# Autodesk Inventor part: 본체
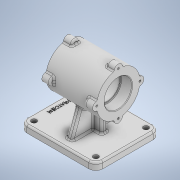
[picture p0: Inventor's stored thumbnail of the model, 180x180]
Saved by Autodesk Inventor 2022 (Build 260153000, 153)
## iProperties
Created: 2023-05
Part Number: 본체
Material: 일반
Document SubType Name: Modeling
Designer: Admin
Density: 1 g/cm^3
Appearance: 기본값
Author: Admin
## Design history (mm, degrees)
sketch "스케치1"
  geometry: L1 (0, -7.4)-(0, 44.4) reference; L2 (-60.9, 0)-(60.9, 0) reference; L3 (-43.5, 0)-(43.5, 0); L4 (43.5, 0)-(43.5, 37); L5 (43.5, 37)-(-43.5, 37); L6 (-43.5, 37)-(-43.5, 0); 2 further points
  constraints: 8 end point, 2 parallel, 1 horizontal, 1 perpendicular, 1 point on line, 1 other
  dimensions: "d4" = 87 distance between parallel lines of L4 L6; "d5" = 74 diameter of L5 L2
revolve "회전1" sketch "스케치1" stored, may be unused: angle "d6" = 90 deg
sketch "스케치2"
  geometry: L1 (-43.5, -37)-(-43.5, 37) reference; L2 (-43.5, 0)-(-24.5, 0); L3 (-24.5, 0)-(-24.5, 23.5); L4 (-24.5, 23.5)-(-43.5, 23.5); L5 (-43.5, 23.5)-(-43.5, 0); L6 (-24.5, 0)-(24.5, 0); L7 (24.5, 0)-(24.5, 21); L8 (24.5, 21)-(-24.5, 21); L9 (-24.5, 21)-(-24.5, 0); L10 (43.5, -37)-(43.5, 37) reference; L11 (24.5, 0)-(43.5, 0); L12 (43.5, 0)-(43.5, 23.5); L13 (43.5, 23.5)-(24.5, 23.5); L14 (24.5, 23.5)-(24.5, 0); L15 (-60.9, 0)-(60.9, 0) reference; 3 further points
  constraints: 24 end point, 6 parallel, 3 horizontal, 3 perpendicular, 2 point on line, 1 midpoint
  dimensions: "d7" = 47 diameter of L4 L15; "d8" = 42 diameter of L8 L15; "d9" = 19 distance between parallel lines of L5 L3; "d10" = 19 distance between parallel lines of L10 L7
revolve "회전2" sketch "스케치2" stored, may be unused: angle "d11" = 90 deg
node "작업 평면1"
sketch "스케치3"
  geometry: L1 (70, -55)-(-60, -55); L2 (-60, -55)-(-60, 55); L3 (-60, 55)-(70, 55); L4 (70, 55)-(70, -55); L5 (89.368, 0)-(-92.632, 0) reference; L6 (0, -67.146)-(0, 86.854) reference; 1 further point
  constraints: 8 end point, 2 parallel, 1 horizontal, 1 perpendicular, 1 other
  dimensions: "d14" = 110 distance between parallel lines of L3 L1; "d58" = 130 distance between parallel lines of L2 L4; "d59" = 70 distance between parallel lines of L6 L4
extrude "돌출1" join sketch "스케치3" distance "d15" = 12; taper "d16" = 0 deg
sketch "스케치4"
  geometry: L1 (-20, 5)-(20, 5); L2 (20, 5)-(20, -5); L3 (20, -5)-(-20, -5); L4 (-20, -5)-(-20, 5); L5 (-96, 0)-(86, 0) reference; L6 (0, 77)-(0, -77) reference; 1 further point
  constraints: 8 end point, 2 parallel, 1 horizontal, 1 perpendicular, 2 other
  dimensions: "d17" = 10 distance between parallel lines of L3 L1; "d18" = 40 distance between parallel lines of L2 L4
extrude "돌출2" join sketch "스케치4" stored distance "d19" = 12; taper "d20" = 0 deg
sketch "스케치5"
  geometry: L1 (0, -105.8)-(0, 60.8) reference; C1 r 7 at (0, 37); 2 further points
  constraints: 1 centre point, 1 point on line, 1 vertical alignment, 1 other
  dimensions: "d21" = 14 diameter of C1
extrude "돌출3" join sketch "스케치5" distance "d22" = 14; taper "d23" = 0 deg
sketch "스케치7"
  geometry: A1 r 7 centre (0, 0) between (6.969, -0.662) and (-6.969, -0.662) reference; A2 r 7 centre (37, -37) between (36.338, -43.969) and (36.338, -30.031) reference; A3 r 7 centre (0, -74) between (-6.969, -73.338) and (6.969, -73.338) reference; A4 r 7 centre (-37, -37) between (-36.338, -30.031) and (-36.338, -43.969) reference; 5 further points
  constraints: 4 coincident
hole "구멍1" sketch "스케치7" at (0, 0), (37, -37), (0, -74), (-37, -37) diameter "d27" = 3.242; stored, may be unused: countersink angle "d31" = 90 deg, drill point angle "d33" = 118 deg; dims "d28" = 8, "d29" = 4, "d30" = 2, "d32" = 10
sketch "스케치8"
  geometry: C1 r 1.621 at (74, 0) reference; C2 r 1.621 at (37, -37) reference; C3 r 1.621 at (0, 0) reference; A1 r 7 centre (37, 37) between (43.969, 36.338) and (30.031, 36.338) reference; A2 r 7 centre (0, 0) between (0.662, 6.969) and (0.662, -6.969) reference; A3 r 7 centre (37, -37) between (30.031, -36.338) and (43.969, -36.338) reference; A4 r 7 centre (74, 0) between (73.338, -6.969) and (73.338, 6.969) reference; 5 further points
  constraints: 4 coincident
hole "구멍2" sketch "스케치8" at (37, 37), (74, 0), (37, -37), (0, 0) diameter "d34" = 3.242; stored, may be unused: countersink angle "d38" = 90 deg, drill point angle "d40" = 118 deg; dims "d35" = 8, "d36" = 4, "d37" = 2, "d39" = 10
sketch "스케치9"
  geometry: L1 (-70, -55)-(-70, 55) reference; L2 (-70, 41)-(-26.964, 25.336); L3 (-82, 55)-(-70, 55) reference; A1 r 37 centre (0, 0) between (-6.969, 36.338) and (-36.338, 6.969) reference; 1 further point
  constraints: 2 end point, 1 point on circle, 1 point on line
  dimensions: "d41" = 110 deg angle of L1 L2; "d42" = 14 distance from line of L2.start L3
feature "리브1" sketch "스케치9" dims "d43" = 1, "d44" = 10, "d45" = 0, "d46" = 0, "d47" = 1, "d48" = 1
fillet "모깎기1" dims "d49" = 12
sketch "스케치10"
  geometry: A1 r 12 centre (-58, 43) between (-58, 55) and (-70, 43) reference; A2 r 12 centre (-58, -43) between (-70, -43) and (-58, -55) reference; A3 r 12 centre (48, 43) between (60, 43) and (48, 55) reference; A4 r 12 centre (48, -43) between (48, -55) and (60, -43) reference; 5 further points
  constraints: 4 coincident
hole "구멍3" sketch "스케치10" at (-58, 43), (48, 43), (48, -43), (-58, -43) diameter "d50" = 9; stored, may be unused: countersink angle "d54" = 90 deg, drill point angle "d56" = 0 deg; dims "d51" = 8, "d52" = 4, "d53" = 2, "d55" = 10
sketch "스케치11"
  geometry: L1 (0, 77)-(0, -77) reference; L2 (-96, 0)-(86, 0) reference; 2 further points
  constraints: 1 other
  dimensions: "d57" = 58 distance from line of L1 point (-58, 1.636)
feature "엠보싱1" dims "d4" = 87, "d5" = 74, "d7" = 47, "d8" = 42, "d9" = 19, "d10" = 19, "d60" = 0.5, "d61" = 0
fillet "모깎기2" dims "d62" = 3
fillet "모깎기3" dims "d63" = 3
fillet "모깎기4" dims "d64" = 1
chamfer "모따기1" distance "d65" = 1; stored, may be unused: second distance "d66" = 2, angle "d67" = 45 deg
node "솔리드1"
pattern_circular "원형 패턴1" dims angle "d25" = 360 deg
mirror "미러1"
mirror "미러2"
feature "A9D066F2-1C7D-4E18-AEED-F7BC21143FA4" dims "d50" = 9, "d51" = 8, "d52" = 4, "d53" = 2, "d54" = 90 deg, "d55" = 10, "d56" = 0
other parameters: "d12" = -82
